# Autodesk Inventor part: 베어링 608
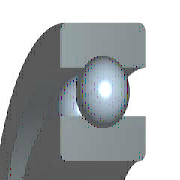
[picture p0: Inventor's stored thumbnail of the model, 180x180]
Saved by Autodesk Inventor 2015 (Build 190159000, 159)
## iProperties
Created: 2012-02
Part Number: 베어링 608
Material: 강철, 연강
Description: 깊은 그루브 볼 베어링
Document SubType Name: Modeling
Standard: KS B 2023
Designer: mduedu
Standards Organization: KS
Language: ko-KR
Size Designation: 608 - 8 x 22 x 7
Categories: <MemberInstance><Categories><Category DisplayName="샤프트 부품" InternalName="7f7aeb1f-a693-4053-b835-cee3144e0d98" Mnemonic="SHFT"><Category DisplayName="베어링" Inter
Density: 7.85 g/cm^3
Appearance: 노란색
Mass: 12.145 g
Surface Area: 20.0754 cm^2
Volume: 1.54714 cm^3
IsCustomPart: 1
Author: mduedu
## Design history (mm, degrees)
sketch "스케치" dims "d0" = 3.64 (= -0.26 x WD + 0.26 x BD)
  geometry: L1 (1.68, 7.5)-(5.32, 7.5); L2 (3.5, 7.5)-(3.5, 5.68); L3 (3.5, 7.5)-(3.5, 9.32); L4 (2.148, 6.282)-(0, 6.282); L5 (0, 4)-(7, 4); L6 (2.148, 8.718)-(0, 8.718); L7 (0, 11)-(7, 11); L8 (7, 4)-(7, 6.282); L9 (4.852, 6.282)-(7, 6.282); L10 (4.852, 8.718)-(7, 8.718); L11 (7, 11)-(7, 8.718); L12 (-1.4, 0)-(8.4, 0) reference; L13 (0, -0.3)-(0, 5.3) reference
  constraints: 22 end point, 4 point on line, 2 collinear, 2 perpendicular, 2 symmetric about line, 1 midpoint, 1 parallel, 14 other
  dimensions: "d9" = 8 diameter of L5 L12 (= WD); "d11" = 22 diameter of L7 L12 (= BD); "d12" = 7 distance between parallel lines of L8 L13 (= KB); "d13" = 12.564 diameter of L9 L12 (= 0.326 x BD + 0.674 x WD)
revolve "본체" stored, may be unused: angle "d6" = 90 deg
revolve "볼" stored, may be unused: angle "d7" = 90 deg
pattern_circular "IDS_ARRAYBALL[SIMPL:T]" dims angle "d3" = 360 deg
body "Solid1"
fillet "모깎기1" dims "d1" = 0.3 (= KRS)
other parameters: "WD" = 8 [user parameter; used in 5 equation terms], "BD" = 22 [user parameter; used in 5 equation terms], "KB" = 7 [user parameter; used in 1 equation term], "KRS" = 0.3 [user parameter; used in 1 equation term], "d4" = 0, "d5" = 0, "d8" = 0, "d14" = 0, "d15" = 0, "BBA" = 0 [user parameter], "BC0" = 1370000 [user parameter], "BC" = 3250000 [user parameter], "BR" = 11 (= 0.5 x BD) [user parameter], "WR" = 4 (= 0.5 x WD) [user parameter]
